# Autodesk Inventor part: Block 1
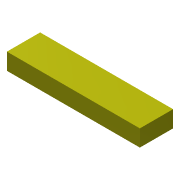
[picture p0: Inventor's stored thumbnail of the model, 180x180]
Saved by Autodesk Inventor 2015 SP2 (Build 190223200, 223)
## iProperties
Created: 2020-01
Part Number: Block 1
Material: 一般
Document SubType Name: Modeling
Designer: Kuan_Lun Hsu
Density: 1 g/cm^3
Appearance: 黃
Author: Kuan_Lun Hsu
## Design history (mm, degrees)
sketch "草圖1"
  geometry: L1 (0, 0)-(40, 0); L2 (40, 0)-(40, 10); L3 (40, 10)-(0, 10); L4 (0, 10)-(0, 0)
  constraints: 8 end point, 2 parallel, 1 horizontal, 1 perpendicular
  dimensions: "d0" = 40 distance of L1.start L1.end; "d1" = 10 distance of L3.end L1.start
extrude "擠出1" new body sketch "草圖1" distance "d2" = 5; taper "d3" = 0 deg
node "實體1"
